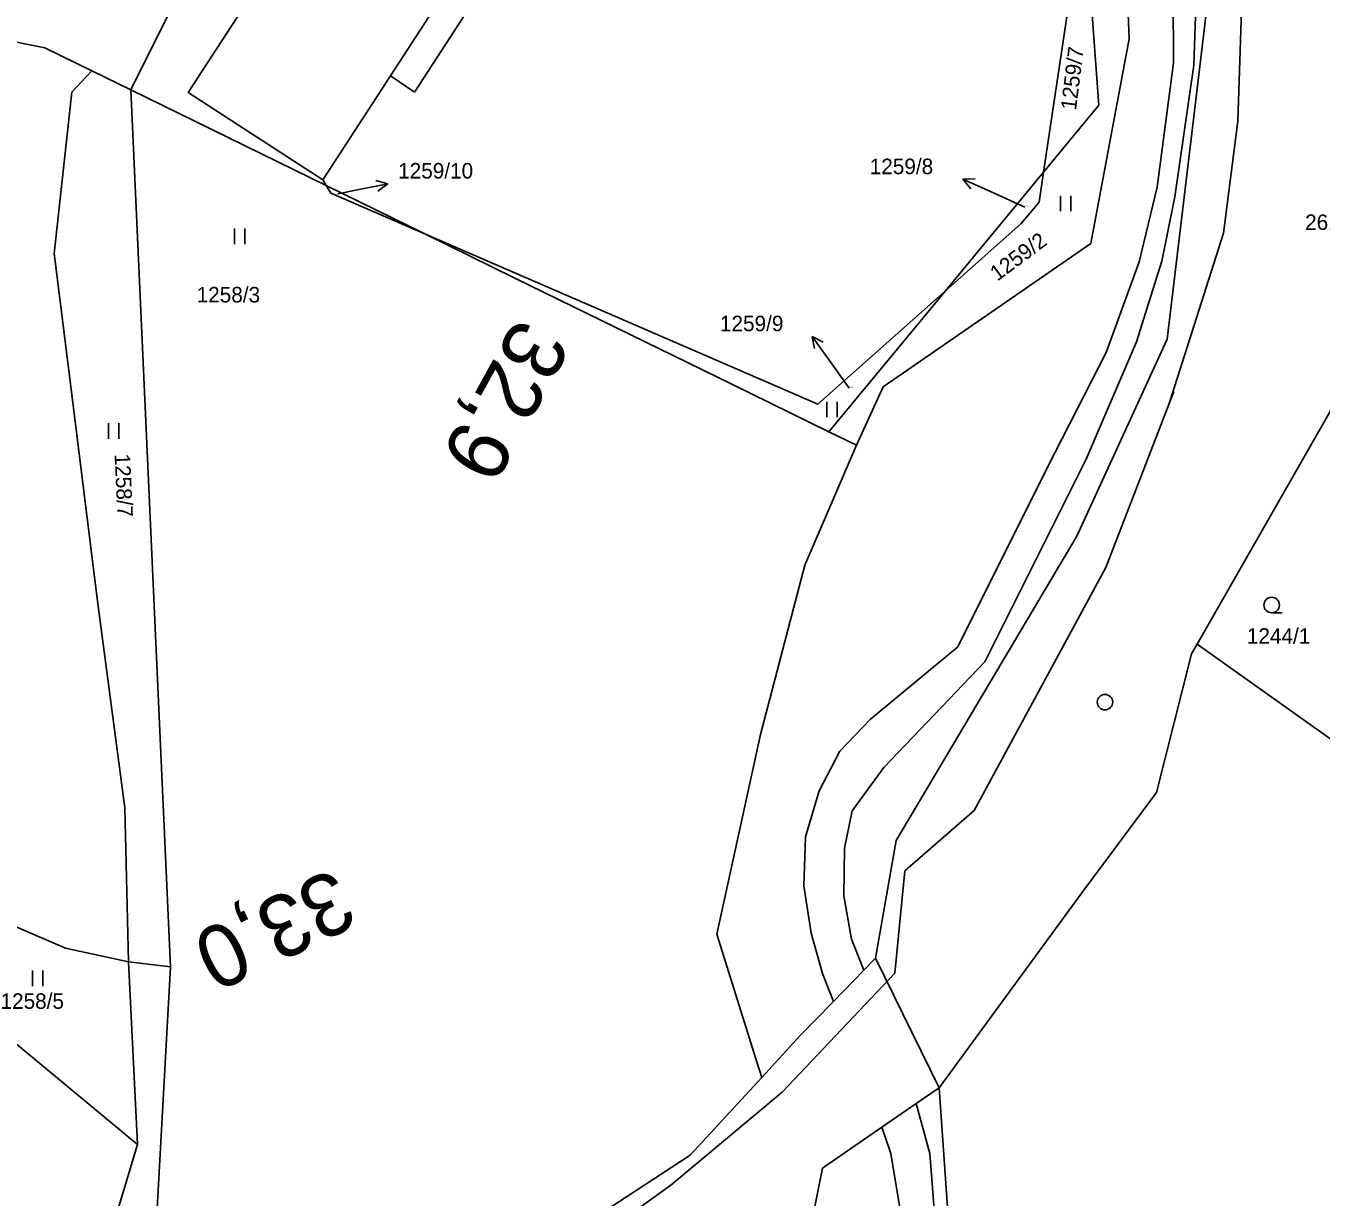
# Model space of a CAD drawing. Extents: x -804166 to -803706, y -1151030 to -1150147.
# Drawn here: x -803978.8 to -803853.6, y -1150693.3 to -1150580.2 of the extents above; entities that cross this region are included whole.
import ezdxf

# ---------------------------------------------------------------- set-up
doc = ezdxf.new("R2010")
doc.units = 0
for name, color, linetype in [('Default', 7, 'Continuous'), ('kilometráž - vrstava 7', 7, 'Continuous'), ('kn_celek - Cisla parcel pomocna', 7, 'Continuous'), ('kn_celek - Cisla pozemkovych parcel', 7, 'Continuous'), ('kn_celek - Hranice parcel', 7, 'Continuous'), ('kn_celek - Vnitrni kresby', 7, 'Continuous'), ('kn_celek - Znacky kultur', 7, 'Continuous'), ('plochy - SZDC', 7, 'Continuous'), ('PSR_C2_2_trasa_Vimperk - Kabelová trasa', 7, 'Continuous')]:
    doc.layers.add(name, color=color, linetype=linetype)

# ---------------------------------------------------------------- blocks, each defined once
blk = doc.blocks.new('304')
at = {"layer": 'Default'}
blk.add_line((-0.1, 0), (9.9, 0), dxfattribs=at)
blk.add_circle((-0.1, 7.5), 7.5, dxfattribs=at)
blk = doc.blocks.new('306')
at = {"layer": 'Default'}
for p, q in [((-5.2, 0), (-5.2, 15)), ((4.8, 0), (4.8, 15))]:
    blk.add_line(p, q, dxfattribs=at)
blk = doc.blocks.new('Z61')
at = {"layer": 'Default'}
for p, q in [((0, 0), (30, 0)), ((30, 0), (19.2, 5.3)), ((30, 0), (19.2, -5.3))]:
    blk.add_line(p, q, dxfattribs=at)

msp = doc.modelspace()

# ---------------------------------------------------------------- linework, layer by layer
at = {"layer": 'kilometráž - vrstava 7'}
msp.add_circle((-803874.49, -1150645.51), 0.75, dxfattribs=at)
at = {"layer": 'kn_celek - Cisla parcel pomocna'}
for p, q in [((-803948.64, -1150596.37), (-803946.76, -1150595.99)), ((-803882.23, -1150597.66), (-803885.49, -1150596.2)), ((-803899.22, -1150615.16), (-803901.04, -1150612.6))]:
    msp.add_line(p, q, dxfattribs=at)
at = {"layer": 'kn_celek - Hranice parcel'}
for p, q in [((-803938.33, -1150548.38), (-803963.12, -1150586.6)), ((-803941.24, -1150586.55), (-803922.92, -1150558.39)), ((-803968.67, -1150586.34), (-803955.66, -1150560.2)), ((-803877.12, -1150560.03), (-803875.07, -1150587.8)), ((-803872.16, -1150581.41), (-803872.68, -1150566.63)), ((-803868.49, -1150610.44), (-803863.95, -1150572.75)), ((-803877.66, -1150575.81), (-803880.42, -1150594.27)), ((-803983.74, -1150580.89), (-803976.96, -1150582.28)), ((-803976.96, -1150582.28), (-803972.44, -1150584.49)), ((-803875.86, -1150601.17), (-803872.16, -1150581.41)), ((-803972.44, -1150584.49), (-803974.35, -1150586.54)), ((-803972.44, -1150584.49), (-803968.67, -1150586.34)), ((-803950.11, -1150595.04), (-803943.57, -1150584.97)), ((-803943.57, -1150584.97), (-803941.24, -1150586.55)), ((-803974.35, -1150586.54), (-803976.07, -1150602.16)), ((-803964.82, -1150671.1), (-803968.67, -1150586.34)), ((-803949.78, -1150595.59), (-803968.67, -1150586.34)), ((-803963.12, -1150586.6), (-803950.11, -1150595.04)), ((-803880.42, -1150594.27), (-803875.07, -1150587.8)), ((-803880.42, -1150594.27), (-803889.91, -1150605.74)), ((-803880.42, -1150594.27), (-803880.85, -1150597.18)), ((-803950.11, -1150595.04), (-803949.78, -1150595.59)), ((-803949.78, -1150595.59), (-803949.33, -1150596.33)), ((-803949.78, -1150595.59), (-803940.19, -1150600.28)), ((-803940.19, -1150600.28), (-803949.33, -1150596.33)), ((-803880.85, -1150597.18), (-803882.6, -1150599.25)), ((-803882.6, -1150599.25), (-803889.91, -1150605.74)), ((-803931.54, -1150604.52), (-803940.19, -1150600.28)), ((-803940.19, -1150600.28), (-803902.24, -1150616.7)), ((-803895.94, -1150615.03), (-803875.86, -1150601.17)), ((-803976.07, -1150602.16), (-803974.5, -1150614.73)), ((-803910.57, -1150614.78), (-803931.54, -1150604.52)), ((-803889.91, -1150605.74), (-803902.24, -1150616.7)), ((-803889.91, -1150605.74), (-803901.18, -1150619.38)), ((-803865.58, -1150639.91), (-803847.18, -1150607.67)), ((-803877.2, -1150629.46), (-803868.49, -1150610.44)), ((-803974.5, -1150614.73), (-803971.93, -1150635.48)), ((-803901.18, -1150619.38), (-803910.57, -1150614.78)), ((-803898.51, -1150620.68), (-803895.94, -1150615.03)), ((-803901.18, -1150619.38), (-803898.51, -1150620.68)), ((-803903.51, -1150632.26), (-803898.51, -1150620.68)), ((-803894.67, -1150658.87), (-803877.2, -1150629.46)), ((-803903.51, -1150632.26), (-803907.8, -1150648.62)), ((-803971.93, -1150635.48), (-803969.24, -1150655.71)), ((-803866.11, -1150640.84), (-803865.58, -1150639.91)), ((-803865.58, -1150639.91), (-803864.14, -1150640.93)), ((-803866.11, -1150640.84), (-803869.51, -1150654.24)), ((-803849.18, -1150651.58), (-803864.14, -1150640.93)), ((-803912, -1150667.93), (-803907.8, -1150648.62)), ((-803968.03, -1150688.27), (-804013.68, -1150650.38)), ((-803869.51, -1150654.24), (-803876.72, -1150663.94)), ((-803969.24, -1150655.71), (-803968.89, -1150670.61)), ((-803999.62, -1150658.69), (-803974.99, -1150669.28)), ((-803896.67, -1150670.26), (-803894.67, -1150658.87)), ((-803876.72, -1150663.94), (-803890.53, -1150682.77)), ((-803912, -1150667.93), (-803908.21, -1150680.09)), ((-803974.99, -1150669.28), (-803968.89, -1150670.61)), ((-803968.89, -1150670.61), (-803964.82, -1150671.1)), ((-803968.03, -1150688.27), (-803968.89, -1150670.61)), ((-803967.26, -1150714.81), (-803964.82, -1150671.1)), ((-803897.8, -1150671.42), (-803896.67, -1150670.26)), ((-803890.53, -1150682.77), (-803896.67, -1150670.26)), ((-803900.74, -1150674.44), (-803897.8, -1150671.42)), ((-803903.98, -1150677.77), (-803900.74, -1150674.44)), ((-803907.67, -1150681.78), (-803903.98, -1150677.77)), ((-803908.21, -1150680.09), (-803907.67, -1150681.78)), ((-803914.58, -1150689.29), (-803907.67, -1150681.78)), ((-803892.73, -1150684.29), (-803890.53, -1150682.77)), ((-803889.5, -1150697.18), (-803890.53, -1150682.77)), ((-803896.05, -1150686.58), (-803892.73, -1150684.29)), ((-803901.78, -1150690.55), (-803896.05, -1150686.58)), ((-803968.03, -1150688.27), (-803976.9, -1150717.98)), ((-803939.84, -1150705.78), (-803914.58, -1150689.29)), ((-803901.78, -1150690.55), (-803905.7, -1150709.82))]:
    msp.add_line(p, q, dxfattribs=at)
at = {"layer": 'kn_celek - Vnitrni kresby'}
for p, q in [((-803925.31, -1150556.84), (-803943.57, -1150584.97)), ((-803865.9, -1150583.94), (-803865.36, -1150568.45)), ((-803867.92, -1150570.66), (-803867.87, -1150583.73)), ((-803867.87, -1150583.73), (-803869.43, -1150595.72)), ((-803865.9, -1150583.94), (-803867.75, -1150596.67)), ((-803871.18, -1150602.96), (-803869.43, -1150595.72)), ((-803867.75, -1150596.67), (-803868.98, -1150602.88)), ((-803874.38, -1150611.72), (-803871.18, -1150602.96)), ((-803868.98, -1150602.88), (-803871.44, -1150610.68)), ((-803871.44, -1150610.68), (-803876.3, -1150622.01)), ((-803879.34, -1150621.41), (-803874.38, -1150611.72)), ((-803888.73, -1150640.2), (-803879.34, -1150621.41)), ((-803876.3, -1150622.01), (-803886.09, -1150641.62)), ((-803888.73, -1150640.2), (-803897.16, -1150647.16)), ((-803895.87, -1150651.83), (-803886.09, -1150641.62)), ((-803897.16, -1150647.16), (-803900.12, -1150650.23)), ((-803900.12, -1150650.23), (-803902.12, -1150654.07)), ((-803898.94, -1150656), (-803895.87, -1150651.83)), ((-803902.12, -1150654.07), (-803903.43, -1150658.54)), ((-803899.68, -1150659.63), (-803898.94, -1150656)), ((-803903.43, -1150658.54), (-803903.6, -1150663.27)), ((-803899.72, -1150664.23), (-803899.68, -1150659.63)), ((-803903.6, -1150663.27), (-803902.88, -1150667.84)), ((-803898.99, -1150668.41), (-803899.72, -1150664.23)), ((-803902.88, -1150667.84), (-803901.78, -1150671.74)), ((-803897.8, -1150671.42), (-803898.99, -1150668.41)), ((-803900.74, -1150674.44), (-803901.78, -1150671.74)), ((-803892.73, -1150684.29), (-803891.41, -1150689.12)), ((-803896.05, -1150686.58), (-803895.2, -1150689.12)), ((-803895.2, -1150689.12), (-803894.23, -1150694.97)), ((-803890.85, -1150696.47), (-803891.41, -1150689.12))]:
    msp.add_line(p, q, dxfattribs=at)
at = {"layer": 'plochy - SZDC'}
for p, q in [((-803863.95, -1150572.75), (-803868.49, -1150610.44)), ((-803865.58, -1150639.91), (-803847.18, -1150607.67)), ((-803868.49, -1150610.44), (-803877.2, -1150629.46)), ((-803877.2, -1150629.46), (-803894.67, -1150658.87)), ((-803866.11, -1150640.84), (-803865.58, -1150639.91)), ((-803869.51, -1150654.24), (-803866.11, -1150640.84)), ((-803876.72, -1150663.94), (-803869.51, -1150654.24)), ((-803894.67, -1150658.87), (-803896.67, -1150670.26)), ((-803890.53, -1150682.77), (-803876.72, -1150663.94)), ((-803896.67, -1150670.26), (-803897.8, -1150671.42)), ((-803896.67, -1150670.26), (-803890.53, -1150682.77)), ((-803890.53, -1150682.77), (-803896.67, -1150670.26)), ((-803897.8, -1150671.42), (-803900.74, -1150674.44)), ((-803900.74, -1150674.44), (-803903.98, -1150677.77)), ((-803903.98, -1150677.77), (-803907.67, -1150681.78)), ((-803907.67, -1150681.78), (-803914.58, -1150689.29)), ((-803892.73, -1150684.29), (-803890.53, -1150682.77)), ((-803896.05, -1150686.58), (-803892.73, -1150684.29)), ((-803901.78, -1150690.55), (-803896.05, -1150686.58)), ((-803914.58, -1150689.29), (-803939.84, -1150705.78)), ((-803905.7, -1150709.82), (-803901.78, -1150690.55))]:
    msp.add_line(p, q, dxfattribs=at)
at = {"layer": 'PSR_C2_2_trasa_Vimperk - Kabelová trasa'}
for points in [[(-803868.21, -1150616.46), (-803863.02, -1150600.18), (-803861.64, -1150589.37), (-803861, -1150569.82), (-803861.33, -1150559.18)], [(-803893.85, -1150661.82), (-803887.13, -1150655.98), (-803874.41, -1150632.5), (-803867.83, -1150615.47)], [(-803940.06, -1150706.11), (-803933.55, -1150703.31), (-803923.82, -1150697.47), (-803916.47, -1150692.18), (-803905.7, -1150683.2), (-803894.81, -1150671.7), (-803893.85, -1150661.82)]]:
    msp.add_lwpolyline(points, dxfattribs=at)

# ---------------------------------------------------------------- block references
at = {"layer": 'kn_celek - Cisla parcel pomocna'}
for p, xscale, yscale, rotation in [((-803946.76, -1150595.99), 0.10000000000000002, 0.1, 11.378610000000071), ((-803885.49, -1150596.2), 0.1, 0.09999999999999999, 155.93130000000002), ((-803901.04, -1150612.6), 0.1, 0.10000000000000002, 125.45082000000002)]:
    msp.add_blockref('Z61', p, dxfattribs=dict(at, xscale=xscale, yscale=yscale, rotation=rotation))
at = {"layer": 'kn_celek - Znacky kultur', "xscale": 0.1, "yscale": 0.10000000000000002}
for name, p in [('306', (-803878.28, -1150598.06)), ('306', (-803958.11, -1150601.24)), ('306', (-803900.85, -1150617.97)), ('306', (-803970.31, -1150620.05)), ('304', (-803858.36, -1150636.87)), ('306', (-803977.66, -1150672.95))]:
    msp.add_blockref(name, p, dxfattribs=at)

# ---------------------------------------------------------------- texts
at = {"layer": 'kilometráž - vrstava 7'}
for s, rotation, p in [('32,9', 241.2248, (-803931.28, -1150608.11)), ('33,0', 205.6225, (-803949, -1150661.46))]:
    msp.add_text(s, height=6, rotation=rotation, dxfattribs=at).set_placement(p)
at = {"layer": 'kn_celek - Cisla parcel pomocna'}
for s, p in [('1259/10', (-803942.82, -1150594.9)), ('1259/8', (-803897.23, -1150594.48)), ('1259/9', (-803911.71, -1150609.66))]:
    msp.add_text(s, height=1.5, dxfattribs=at).set_placement(p)
at = {"layer": 'kn_celek - Cisla pozemkovych parcel'}
for s, rotation, p in [('1259/7', 82.8, (-803877.29, -1150588.35)), ('1259/2', 36.6344, (-803884.89, -1150604.87)), ('1258/7', 272.7, (-803970.24, -1150621.53))]:
    msp.add_text(s, height=1.5, rotation=rotation, dxfattribs=at).set_placement(p)
for s, height, p in [('1259/10', 0.1, (-803948.64, -1150596.34)), ('1259/8', 0.1, (-803882.23, -1150597.63)), ('2616/1', 1.5, (-803855.14, -1150599.87)), ('1258/3', 1.5, (-803962.3, -1150606.88)), ('1259/9', 0.1, (-803899.22, -1150615.13)), ('1244/1', 1.5, (-803860.77, -1150639.86)), ('1258/5', 1.5, (-803981.26, -1150675.15))]:
    msp.add_text(s, height=height, dxfattribs=at).set_placement(p)

doc.saveas('drawing.dxf')
